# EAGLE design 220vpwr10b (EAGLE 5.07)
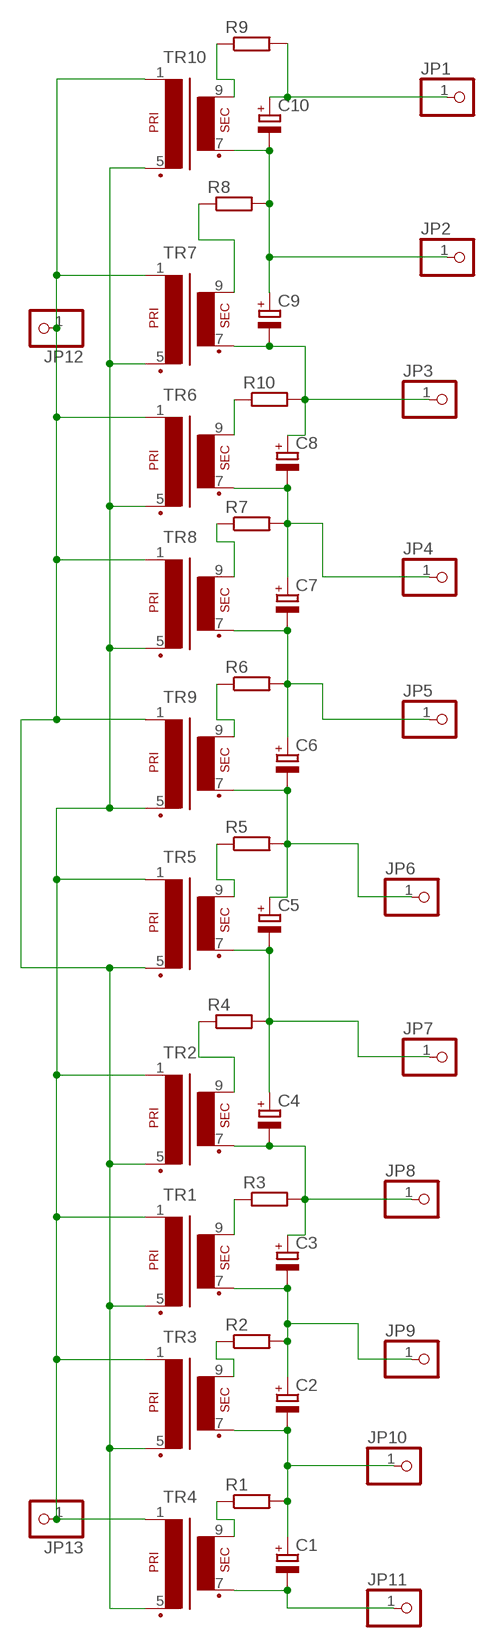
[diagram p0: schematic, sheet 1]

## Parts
C1  CPOL-EUE3.5-8  [E3,5-8]
C2  CPOL-EUE3.5-8  [E3,5-8]
C3  CPOL-EUE3.5-8  [E3,5-8]
C4  CPOL-EUE3.5-8  [E3,5-8]
C5  CPOL-EUE3.5-8  [E3,5-8]
C6  CPOL-EUE3.5-8  [E3,5-8]
C7  CPOL-EUE3.5-8  [E3,5-8]
C8  CPOL-EUE3.5-8  [E3,5-8]
C9  CPOL-EUE3.5-8  [E3,5-8]
C10  CPOL-EUE3.5-8  [E3,5-8]
JP1  PINHD-1X11MM6  [1X1MM8]
JP2  PINHD-1X11MM6  [1X1MM8]
JP3  PINHD-1X11MM6  [1X1MM8]
JP4  PINHD-1X11MM6  [1X1MM8]
JP5  PINHD-1X11MM6  [1X1MM8]
JP6  PINHD-1X11MM6  [1X1MM8]
JP7  PINHD-1X11MM6  [1X1MM8]
JP8  PINHD-1X11MM6  [1X1MM8]
JP9  PINHD-1X11MM6  [1X1MM8]
JP10  PINHD-1X11MM6  [1X1MM8]
JP11  PINHD-1X11MM6  [1X1MM8]
JP12  PINHD-1X11MM6  [1X1MM8]
JP13  PINHD-1X11MM6  [1X1MM8]
R1  R-EU_R1210  [R1210]
R2  R-EU_R1210  [R1210]
R3  R-EU_R1210  [R1210]
R4  R-EU_R1210  [R1210]
R5  R-EU_R1210  [R1210]
R6  R-EU_R1210  [R1210]
R7  R-EU_R1210  [R1210]
R8  R-EU_R1210  [R1210]
R9  R-EU_R1210  [R1210]
R10  R-EU_R1210  [R1210]
TR1  VR11  [1X3WDIRVER]
TR2  VR11  [1X3WDIRVER]
TR3  VR11  [1X3WDIRVER]
TR4  VR11  [1X3WDIRVER]
TR5  VR11  [1X3WDIRVER]
TR6  VR11  [1X3WDIRVER]
TR7  VR11  [1X3WDIRVER]
TR8  VR11  [1X3WDIRVER]
TR9  VR11  [1X3WDIRVER]
TR10  VR11  [1X3WDIRVER]

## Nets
N$1: C1.+ C2.- JP10.1 R1.2 TR3.7(S3)
N$2: C2.+ C3.- JP9.1 R2.2 TR1.7(S3)
N$3: C3.+ C4.- JP8.1 R3.2 TR2.7(S3)
N$4: C4.+ C5.- JP7.1 R4.2 TR5.7(S3)
N$5: JP12.1 TR1.5(P2) TR2.5(P2) TR3.5(P2) TR4.5(P2) TR5.5(P2) TR6.1 TR7.1 TR8.1 TR9.1 TR10.1
N$6: JP13.1 TR1.1 TR2.1 TR3.1 TR4.1 TR5.1 TR6.5(P2) TR7.5(P2) TR8.5(P2) TR9.5(P2) TR10.5(P2)
N$7: C7.+ C8.- JP4.1 R7.2 TR6.7(S3)
N$8: C8.+ C9.- JP3.1 R10.2 TR7.7(S3)
N$9: C6.+ C7.- JP5.1 R6.2 TR8.7(S3)
N$10: C9.+ C10.- JP2.1 R8.2 TR10.7(S3)
N$11: C10.+ JP1.1 R9.2
N$12: C1.- JP11.1 TR4.7(S3)
N$13: C5.+ C6.- JP6.1 R5.2 TR9.7(S3)
N$14: R9.1 TR10.9(S4)
N$15: R8.1 TR7.9(S4)
N$16: R10.1 TR6.9(S4)
N$17: R7.1 TR8.9(S4)
N$18: R6.1 TR9.9(S4)
N$19: R5.1 TR5.9(S4)
N$20: R4.1 TR2.9(S4)
N$21: R3.1 TR1.9(S4)
N$22: R2.1 TR3.9(S4)
N$23: R1.1 TR4.9(S4)

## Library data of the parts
C1-C10 = rcl:CPOL-EU: POLARIZED CAPACITOR, European symbol
JP1-JP13 = pinhead:PINHD-1X1: PIN HEADER
R1-R10 = rcl:R-EU_: RESISTOR, European symbol
TR1-TR10 = trafo:VR11: TRANSFORMER 1 primary winding, 1 secondary winding BLOCK

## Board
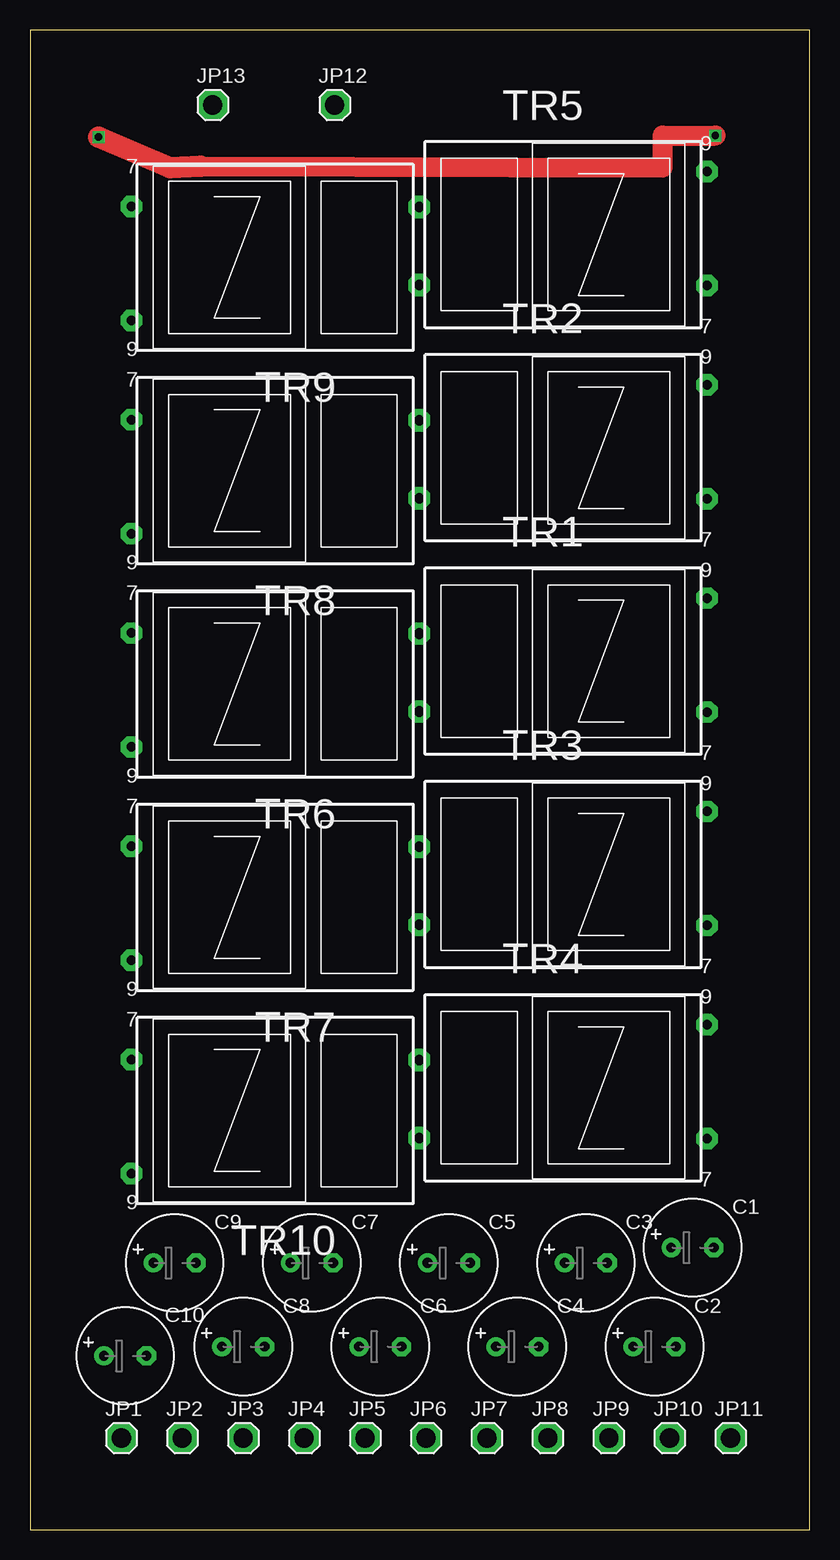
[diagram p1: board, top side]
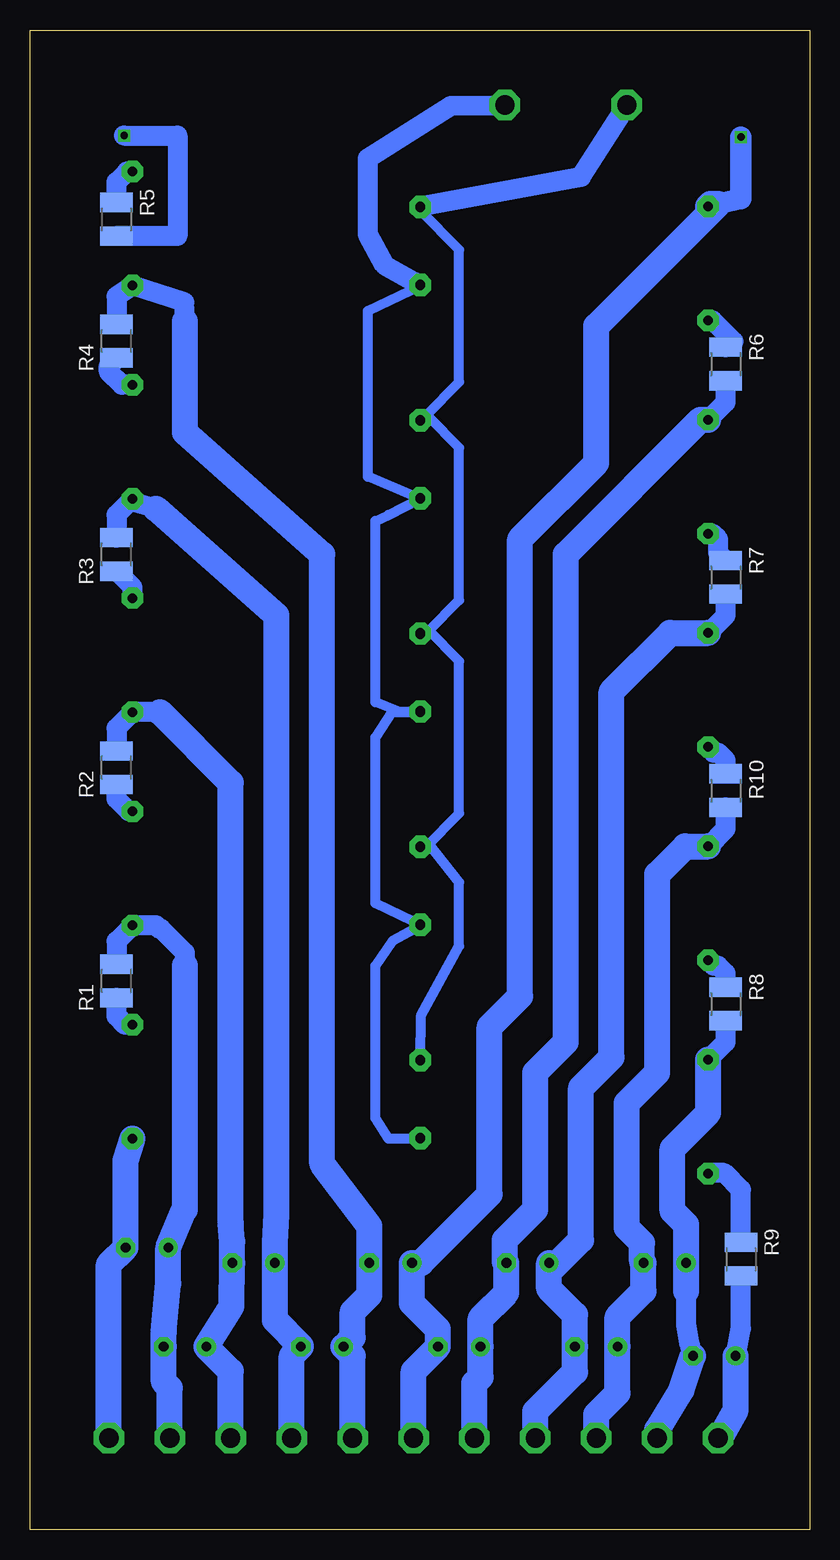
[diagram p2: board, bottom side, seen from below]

Size 65 x 125 mm. Coordinates in mm from the lower left corner, seen from the top.
Outline: 0,0 65,0 65,125 0,125 0,0
Copper layers (1*16): Top 0.035mm / dielectric 1.5mm / Bottom 0.035mm
Design rules "default": minimum track width 10mil, minimum drill 20mil, track to track 8mil, track to pad 8mil, pad to pad 8mil, via to via 8mil, smd to smd 8mil, copper to edge 40mil, drill to drill 8mil, minimum pad ring 1mil, minimum via ring 8mil, stop-mask expansion 4mil, vias tented up to drill 0mil, thermal gap 10mil

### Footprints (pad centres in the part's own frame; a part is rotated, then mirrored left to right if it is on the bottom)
E3,5-8 = drill 0.813 pad 1.6 round: + -1.778,0 | drill 0.813 pad 1.6 octagon: - 1.778,0
1X1MM8 = drill 1.6 pad 2.54 octagon: 1 0,0
R1210 = smd 1.6 x 2.7: 1 -1.4,0; 2 1.4,0
1X3WDIRVER = drill 0.8 pad 1.778 octagon: 1 -12,2.25; 5 -12,-4.25; 7 12,-4.25; 9 12,5.25

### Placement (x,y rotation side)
C1  55.24,23.5 0 top
C2  52.07,15.24 0 top
C3  46.35,22.23 0 top
C4  40.64,15.24 0 top
C5  34.92,22.23 0 top
C6  29.21,15.24 0 top
C7  23.5,22.23 0 top
C8  17.78,15.24 0 top
C9  12.06,22.23 0 top
C10  7.94,14.48 0 top
JP1  7.62,7.62 0 top
JP2  12.7,7.62 0 top
JP3  17.78,7.62 0 top
JP4  22.86,7.62 0 top
JP5  27.94,7.62 0 top
JP6  33.02,7.62 0 top
JP7  38.1,7.62 0 top
JP8  43.18,7.62 0 top
JP9  48.26,7.62 0 top
JP10  53.34,7.62 0 top
JP11  58.42,7.62 0 top
JP12  25.4,118.75 0 top
JP13  15.24,118.75 0 top
R1  57.78,45.72 90 bottom
R2  57.78,63.5 90 bottom
R3  57.78,81.28 90 bottom
R4  57.78,99.06 90 bottom
R5  57.78,109.22 270 bottom
R6  6.99,97.16 270 bottom
R7  6.99,79.38 270 bottom
R8  6.99,43.81 270 bottom
R9  5.71,22.54 270 bottom
R10  6.99,61.59 270 bottom
TR1  44.45,72.39 0 top
TR2  44.45,90.17 0 top
TR3  44.45,54.61 0 top
TR4  44.45,36.83 0 top
TR5  44.45,107.95 0 top
TR6  20.45,70.48 180 top
TR7  20.45,52.7 180 top
TR8  20.45,88.27 180 top
TR9  20.45,106.05 180 top
TR10  20.45,34.92 180 top

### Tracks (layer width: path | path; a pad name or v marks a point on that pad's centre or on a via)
N$1
  Bottom 1.676: R1.2 57.78,49.02 TR3.7 54.48,50.35 54.23,50.1 54.1,50.1 52.07,48.07 52.07,46.99
  Bottom 2.184: JP10.1 53.34,11.81 53.85,12.32 C2.- 53.85,16.45 53.47,20.51 C1.+ 52.2,26.54 52.07,26.67 52.07,46.99
N$2
  Bottom 1.676: 54.17,68.14 TR1.7 57.78,66.81 R2.2
  Bottom 2.184: JP9.1 48.26,13.21 C2.+ 48.2,18.61 C3.- 48.13,24 48.26,25.53 48.26,62.23 54.17,68.14
N$3
  Bottom 1.676: R3.2 57.78,84.58 TR2.7 56.45,85.66 54.48,85.09
  Bottom 2.184: 54.48,85.09 44.45,76.2 44.45,26.29 44.58,23.88 C3.+ 44.58,17.46 42.42,15.3 C4.- 43.18,14.48 JP8.1
N$4
  Bottom 1.676: R4.2 57.78,102.81 TR5.7 52.13,102.31 52.07,100.71
  Bottom 2.184: 52.07,100.71 52.07,91.44 40.64,81.28 40.64,30.48 36.7,25.27 C5.- 36.7,19.56 38.1,18.16 38.1,16 C4.+ 38.1,14.48 JP7.1
N$5
  Bottom 0.813: TR5.5 36.83,101.6 36.83,96.52 36.83,87.76 33.09,86.19 | 33.09,86.19 TR2.5 35.12,84.58 36.2,84.07 36.2,68.96 34.16,68.14 TR1.5 33.02,68.14 | 33.02,68.14 34.79,68.14 36.2,66.04 36.2,52.2 33.08,50.67 | 33.08,50.67 TR3.5 34.73,49.09 36.2,46.99 36.2,34.29 35.12,32.58 TR4.5 | TR7.1 32.87,50.45 33.08,50.67 | TR6.1 32.92,68.23 33.02,68.14 | TR8.1 32.92,86.02 33.09,86.19 | TR9.1 32.81,103.8 33.07,104.06 | 33.07,104.06
  Bottom 1.676: JP12.1 29.91,118.68 36.83,114.3 36.83,107.95 35.43,105.41 33.07,104.06 TR5.5 | TR4.5 TR10.1
N$6
  Bottom 0.813: 31.95,92.92 TR2.1 | 31.95,92.92 29.21,95.66 29.21,106.68 32.45,109.92 TR5.1 TR9.5 | TR1.1 TR6.5 32.25,74.93 31.75,74.93 | TR7.5 32.25,57.15 31.75,57.15 29.21,53.98 29.21,48.64 32.38,42.86 TR10.5 TR4.1 | TR7.5 31.95,56.95 29.21,59.69 29.21,72.39 31.75,74.93 | 31.75,74.93 29.21,77.47 29.21,90.17 31.75,92.71 | 31.75,92.71 31.95,92.92 | TR7.5 TR3.1 | TR8.5 31.95,92.52 31.75,92.71
  Bottom 1.676: JP13.1 19.05,112.77 TR9.5
N$7
  Bottom 0.813: 21.72,21.59 21.59,21.59
  Bottom 1.676: R7.2 6.99,76.2 TR6.7
  Bottom 2.184: JP4.1 22.86,9.84 19.56,13.14 C8.- 19.56,17.91 21.72,20.07 21.72,21.59 C7.+ | TR6.7 11.62,74.73 16.51,69.85 16.51,39.37 19.05,36.83 19.05,24.13 21.59,21.59 21.59,22.1
N$8
  Bottom 1.676: R10.2 6.99,58.42 TR7.7
  Bottom 2.184: JP3.1 17.78,9.59 16,11.37 C8.+ 16,17.72 13.84,19.88 C9.- 13.97,22.35 13.97,23.88 15.24,25.15 15.24,35.56 12.7,38.1 12.7,54.61 10.36,56.95 TR7.7
N$9
  Bottom 1.676: R6.2 6.99,93.98 TR8.7
  Bottom 2.184: JP5.1 27.94,12.19 27.43,12.7 C6.+ 27.43,17.59 25.27,19.75 C7.- 25.4,22.35 25.4,24.13 22.86,26.67 22.86,38.1 20.32,40.64 20.32,81.28 9.09,92.52 TR8.7
N$10
  Bottom 1.676: C10.- 9.97,15.37 10.29,17.08 10.29,19.88 | R8.2 6.99,40.64 TR10.7
  Bottom 2.184: JP2.1 12.7,8.32 10.67,11.62 C10.- | 10.29,19.88 C9.+ 10.29,25.4 11.43,26.54 11.43,31.75 8.45,34.73 TR10.7
N$11
  Bottom 1.676: C10.+ 5.71,16.76 R9.2
  Bottom 2.184: JP1.1 7.49,7.62 6.16,9.97 C10.+
N$12
  Bottom 2.184: JP11.1 58.42,22.1 C1.- 57.02,30.74 TR4.7
N$13  (via drill 0.6)
  Top 1.676: 14.23,113.67 52.77,113.54 52.77,116.2 v57.15,116.2
  Top 1.778: v5.71,116.08 11.69,113.54 14.23,113.67
  Bottom 1.676: R5.2 52.7,107.82 52.7,116.2 v57.15,116.2
  Bottom 1.778: TR9.7 5.71,110.93 v5.71,116.08
  Bottom 2.184: JP6.1 33.02,13.21 C6.- 30.99,16.7 33.15,18.86 C5.+ 32.38,22.23 26.67,27.94 26.67,41.91 24.13,44.45 24.13,82.55 17.78,88.9 17.78,100.33 7.62,110.49 8.25,110.49 TR9.7
N$14
  Bottom 1.676: R9.1 5.71,28.32 7.11,29.72 8.4,29.72 TR10.9
N$15
  Bottom 1.676: R8.1 6.99,46.35 7.62,46.99 7.98,46.99 TR7.9
N$16
  Bottom 1.676: R10.1 6.99,64.14 7.62,64.77 7.98,64.77 TR6.9
N$17
  Bottom 1.676: TR8.9 8.09,83.02 7.62,82.55 7.62,81.41 R7.1
N$18
  Bottom 1.676: TR9.9 8.09,100.8 6.35,99.06 6.48,99.06 R6.1
N$19
  Bottom 1.676: TR5.9 56.92,113.2 57.78,112.33 R5.1
N$20
  Bottom 1.676: TR2.9 57.32,95.42 58.42,96.52 58.42,97.03 R4.1
N$21
  Bottom 1.676: TR1.9 56.45,78.55 R3.1
N$22
  Bottom 1.676: TR3.9 56.75,59.86 57.78,60.9 R2.1
N$23
  Bottom 1.676: TR4.9 57.07,42.08 57.78,42.8 R1.1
